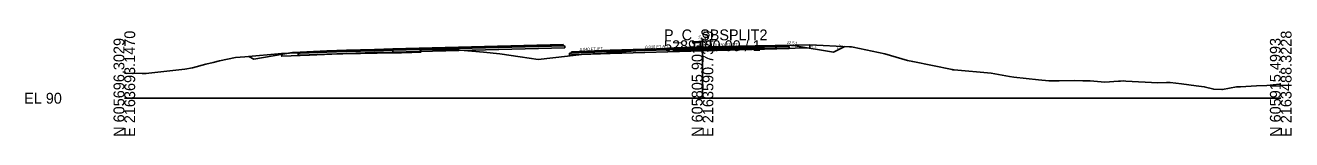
# Model space of a CAD drawing. Extents: x -26 to 1303, y -10 to 12033.
# Drawn here: x -25.7 to 302.8, y 4990.3 to 5017.8 of the extents above; entities that cross this region are included whole.
import ezdxf

# ---------------------------------------------------------------- set-up
doc = ezdxf.new("R2010")
doc.units = 0
for name, color, linetype in [('RD_GPK_XS_Cell', 7, 'Continuous'), ('RD_XS_Base', 7, 'Continuous'), ('RD_XS_ExGround', 7, 'Continuous'), ('RD_XS_ExPaveRet', 7, 'Continuous'), ('RD_XS_Greenside', 7, 'Continuous'), ('RD_XS_Pave', 7, 'Continuous'), ('RD_XS_PaveOvlay_CP', 7, 'Continuous'), ('RD_XS_TieSlope', 7, 'Continuous'), ('RD_XS_TX_Elev_EX', 7, 'Continuous'), ('RD_XS_TX_Elev_PR', 7, 'Continuous'), ('RD_XS_TX_ShdSlope', 7, 'Continuous'), ('RD_XS_TX_Slope', 7, 'Continuous')]:
    doc.layers.add(name, color=color, linetype=linetype)

msp = doc.modelspace()

# ---------------------------------------------------------------- linework, layer by layer
at = {"layer": 'RD_GPK_XS_Cell'}
for p, q in [((150, 5000), (150, 5015)), ((0, 5000), (150, 5000)), ((150, 5000), (300, 5000))]:
    msp.add_line(p, q, dxfattribs=at)
at = {"layer": 'RD_XS_Base'}
for p, q in [((69.61, 5012.43), (114.3, 5013.59)), ((113.8, 5013.58), (113.8, 5013.58)), ((114.3, 5013.59), (114.3, 5013.09)), ((114.3, 5013.56), (114.3, 5013.56)), ((172.5, 5013.41), (172.5, 5012.91)), ((45.39, 5011.63), (45.11, 5011.62)), ((45.11, 5011.62), (45.11, 5011.4)), ((45.11, 5011.4), (45.11, 5011.12)), ((45.11, 5011.12), (45.39, 5011.13)), ((45.61, 5011.64), (45.39, 5011.63)), ((45.39, 5011.13), (45.61, 5011.14)), ((52.56, 5011.92), (45.61, 5011.64)), ((45.61, 5011.14), (52.56, 5011.42)), ((57.61, 5012.12), (52.56, 5011.92)), ((52.56, 5011.42), (57.61, 5011.62)), ((64.91, 5012.31), (57.61, 5012.12)), ((57.61, 5011.62), (64.91, 5011.81)), ((69.61, 5012.43), (64.91, 5012.31)), ((64.91, 5011.81), (69.61, 5011.93)), ((114.3, 5013.09), (69.61, 5011.93)), ((69.61, 5011.93), (69.61, 5012.59)), ((69.61, 5012.59), (69.61, 5012.59)), ((69.61, 5012.59), (69.61, 5012.59)), ((69.61, 5012.59), (69.61, 5012.43)), ((69.61, 5012.43), (69.61, 5012.43)), ((69.61, 5011.93), (69.61, 5012.43)), ((69.61, 5012.43), (69.61, 5012.43)), ((69.61, 5012.43), (69.61, 5012.43)), ((69.61, 5011.93), (69.61, 5011.93)), ((93.61, 5013.06), (93.61, 5013.06)), ((93.61, 5013.06), (93.61, 5013.06)), ((93.61, 5012.56), (93.61, 5012.56)), ((93.61, 5012.56), (93.61, 5012.56)), ((116, 5011.71), (115.5, 5011.69)), ((115.5, 5011.69), (115.5, 5011.69)), ((115.5, 5011.69), (115.5, 5011.19)), ((115.5, 5011.19), (116, 5011.21)), ((126, 5012.11), (116, 5011.71)), ((116, 5011.71), (116, 5011.71)), ((116, 5011.21), (126, 5011.61)), ((116, 5011.21), (116, 5011.21)), ((150, 5012.78), (126, 5012.11)), ((126, 5011.61), (150, 5012.28)), ((126, 5012.11), (126, 5012.11)), ((126, 5011.61), (126, 5011.61)), ((150, 5012.78), (172, 5013.39)), ((150, 5012.28), (150, 5012.94)), ((150, 5012.94), (150, 5012.94)), ((150, 5012.94), (150, 5012.94)), ((150, 5012.94), (150, 5012.78)), ((172.5, 5012.91), (150, 5012.28)), ((150, 5012.78), (150, 5012.78)), ((150, 5012.28), (150, 5012.78)), ((150, 5012.78), (150, 5012.78)), ((150, 5012.78), (150, 5012.78)), ((150, 5012.28), (150, 5012.28)), ((162, 5013.11), (162, 5013.11)), ((162, 5013.11), (162, 5013.11)), ((162, 5012.61), (162, 5012.61)), ((162, 5012.61), (162, 5012.61)), ((172, 5013.39), (172, 5013.39)), ((172.5, 5013.37), (172.5, 5013.37))]:
    msp.add_line(p, q, dxfattribs=at)
at = {"layer": 'RD_XS_ExGround'}
msp.add_lwpolyline([(0, 5006.53), (4.66, 5006.44), (5.67, 5006.44), (6.31, 5006.51), (15.68, 5007.53), (17.65, 5007.89), (21.17, 5008.82), (23, 5009.26), (24.69, 5009.69), (28.82, 5010.51), (31.24, 5010.72), (40.84, 5011.6), (58.79, 5012.34), (59.16, 5012.35), (59.38, 5012.35), (60.86, 5012.36), (60.94, 5012.36), (61.19, 5012.36), (61.72, 5012.38), (62.25, 5012.38), (66.75, 5012.49), (71.93, 5012.54), (76.88, 5012.64), (83.64, 5012.53), (85.15, 5012.5), (87.13, 5012.43), (93.18, 5011.93), (97.43, 5011.5), (102.71, 5010.73), (107.34, 5010.07), (114.99, 5010.92), (118.61, 5011.3), (121.5, 5011.53), (123.5, 5011.52), (126.58, 5011.84), (133.91, 5012.36), (141.14, 5012.93), (142.63, 5013.03), (145.13, 5013.1), (151.45, 5013.27), (152.91, 5013.32), (155.38, 5013.35), (158.18, 5013.4), (159.67, 5013.48), (159.87, 5013.5), (160.14, 5013.5), (163.67, 5013.57), (174, 5013.73), (177.87, 5013.8), (188.14, 5013.29), (188.68, 5013.27), (189.08, 5013.18), (197.3, 5011.52), (197.32, 5011.51), (203.19, 5009.81), (204.53, 5009.5), (214.76, 5007.41), (214.93, 5007.37), (215.31, 5007.34), (224.86, 5006.49), (229.6, 5005.67), (230.79, 5005.49), (237.15, 5004.73), (239.8, 5004.49), (242.52, 5004.49), (246.46, 5004.62), (248.63, 5004.47), (250.55, 5004.49), (254.41, 5004.12), (257.91, 5004.42), (258.45, 5004.44), (259.22, 5004.52), (259.85, 5004.43), (268.09, 5004.02), (270.34, 5004.11), (271.31, 5004.09), (274.27, 5003.71), (278.06, 5003.17), (280.16, 5002.96), (282.61, 5002.34), (284.71, 5002.25), (284.85, 5002.25), (284.93, 5002.27), (288.56, 5002.91), (289.55, 5002.92), (293.69, 5003.23), (296.36, 5003.33), (299.66, 5003.6), (300, 5003.62)], dxfattribs=at)
at = {"layer": 'RD_XS_ExPaveRet'}
for points in [[(177.87, 5013.8), (177.87, 5013.05), (177.87, 5013.05), (177.87, 5013.05), (174, 5012.98), (174, 5012.98), (163.67, 5012.82), (163.67, 5012.82), (160.14, 5012.75), (160.14, 5012.75), (159.87, 5012.75), (159.67, 5012.73), (159.67, 5012.73), (158.18, 5012.65), (158.18, 5012.65), (158.18, 5012.65), (158.18, 5012.65), (155.38, 5012.6), (155.38, 5012.6), (152.91, 5012.57), (151.45, 5012.52), (151.45, 5012.52), (145.13, 5012.35), (145.13, 5012.35), (142.63, 5012.28), (142.63, 5013.03), (142.63, 5013.03), (145.13, 5013.1), (145.13, 5013.1), (151.45, 5013.27), (151.45, 5013.27), (152.91, 5013.32), (155.38, 5013.35), (155.38, 5013.35), (158.18, 5013.4), (158.18, 5013.4), (158.18, 5013.4), (158.18, 5013.4), (159.67, 5013.48), (159.67, 5013.48), (159.87, 5013.5), (160.14, 5013.5), (160.14, 5013.5), (163.67, 5013.57), (163.67, 5013.57), (174, 5013.73), (174, 5013.73), (177.87, 5013.8), (177.87, 5013.8)], [(177.87, 5013.8), (174, 5013.73), (163.67, 5013.57), (160.14, 5013.5), (159.87, 5013.5), (159.67, 5013.48), (158.18, 5013.4), (155.38, 5013.35), (152.91, 5013.32), (151.45, 5013.27), (145.13, 5013.1), (142.63, 5013.03), (142.63, 5012.28), (145.13, 5012.35), (151.45, 5012.52), (152.91, 5012.57), (155.38, 5012.6), (158.18, 5012.65), (159.67, 5012.73), (159.87, 5012.75), (160.14, 5012.75), (163.67, 5012.82), (174, 5012.98), (177.87, 5013.05), (177.87, 5013.05), (177.87, 5013.8), (177.87, 5013.8)], [(76.88, 5012.64), (76.88, 5012.64), (74.59, 5012.6), (71.93, 5012.54), (68.01, 5012.5), (66.75, 5012.49), (65.6, 5012.46), (64.86, 5012.46), (62.37, 5012.4), (61.63, 5012.38), (61.27, 5012.37), (60.94, 5012.36), (60.83, 5012.36), (60.1, 5012.35), (59.43, 5012.35), (59, 5012.34), (56.71, 5012.26), (55.81, 5012.21), (48.07, 5011.9), (40.84, 5011.6), (40.84, 5011.21), (40.84, 5010.85), (48.07, 5011.15), (55.81, 5011.46), (56.71, 5011.51), (59, 5011.59), (59.43, 5011.6), (60.1, 5011.6), (60.83, 5011.61), (60.94, 5011.61), (61.27, 5011.62), (61.63, 5011.63), (62.37, 5011.65), (64.86, 5011.71), (65.6, 5011.71), (66.75, 5011.74), (68.01, 5011.75), (71.93, 5011.79), (74.59, 5011.85), (76.88, 5011.89), (76.88, 5011.89), (76.88, 5011.89), (76.88, 5012.34), (76.88, 5012.64), (76.88, 5012.64)], [(76.88, 5012.64), (76.88, 5012.64), (74.59, 5012.6), (71.93, 5012.54), (68.01, 5012.5), (66.75, 5012.49), (65.6, 5012.46), (64.86, 5012.46), (62.37, 5012.4), (61.63, 5012.38), (61.27, 5012.37), (60.94, 5012.36), (60.83, 5012.36), (60.1, 5012.35), (59.43, 5012.35), (59, 5012.34), (56.71, 5012.26), (55.81, 5012.21), (48.07, 5011.9), (40.84, 5011.6), (40.84, 5011.21), (40.84, 5010.85), (48.07, 5011.15), (55.81, 5011.46), (56.71, 5011.51), (59, 5011.59), (59.43, 5011.6), (60.1, 5011.6), (60.83, 5011.61), (60.94, 5011.61), (61.27, 5011.62), (61.63, 5011.63), (62.37, 5011.65), (64.86, 5011.71), (65.6, 5011.71), (66.75, 5011.74), (68.01, 5011.75), (71.93, 5011.79), (74.59, 5011.85), (76.88, 5011.89), (76.88, 5011.89), (76.88, 5011.89), (76.88, 5012.34), (76.88, 5012.64), (76.88, 5012.64)]]:
    msp.add_lwpolyline(points, dxfattribs=at)
at = {"layer": 'RD_XS_Greenside'}
for p, q in [((174, 5013.55), (184, 5011.89)), ((33.61, 5010.13), (32.25, 5010.81)), ((43.61, 5011.8), (33.61, 5010.13)), ((184, 5011.89), (186.93, 5013.35))]:
    msp.add_line(p, q, dxfattribs=at)
at = {"layer": 'RD_XS_Pave'}
for p, q in [((113.8, 5013.9), (69.61, 5012.75)), ((113.8, 5013.74), (69.61, 5012.59)), ((69.61, 5012.59), (113.8, 5013.74)), ((69.61, 5012.43), (113.8, 5013.58)), ((113.8, 5013.74), (113.8, 5013.9)), ((113.8, 5013.9), (113.8, 5013.9)), ((113.8, 5013.58), (113.8, 5013.74)), ((113.8, 5013.74), (113.8, 5013.74)), ((172, 5013.71), (150, 5013.1)), ((172, 5013.55), (150, 5012.94)), ((150, 5012.94), (172, 5013.55)), ((150, 5012.78), (172.5, 5013.41)), ((162, 5013.43), (162, 5013.43)), ((162, 5013.43), (162, 5013.43)), ((172, 5013.55), (172, 5013.71)), ((172, 5013.71), (172, 5013.71)), ((172, 5013.39), (172, 5013.55)), ((172, 5013.55), (172, 5013.55)), ((52.56, 5012.24), (45.61, 5011.96)), ((45.61, 5011.8), (52.56, 5012.08)), ((52.56, 5012.08), (45.61, 5011.8)), ((45.61, 5011.96), (45.61, 5011.89)), ((45.61, 5011.64), (52.56, 5011.92)), ((45.61, 5011.89), (45.61, 5011.8)), ((45.61, 5011.8), (45.61, 5011.73)), ((45.61, 5011.73), (45.61, 5011.64)), ((57.61, 5012.44), (52.56, 5012.24)), ((52.56, 5012.08), (57.61, 5012.28)), ((57.61, 5012.28), (52.56, 5012.08)), ((52.56, 5011.92), (57.61, 5012.12)), ((64.91, 5012.63), (57.61, 5012.44)), ((57.61, 5012.28), (64.91, 5012.47)), ((64.91, 5012.47), (57.61, 5012.28)), ((57.61, 5012.12), (64.91, 5012.31)), ((69.61, 5012.75), (64.91, 5012.63)), ((64.91, 5012.47), (69.61, 5012.59)), ((69.61, 5012.59), (64.91, 5012.47)), ((64.91, 5012.31), (69.61, 5012.43)), ((69.61, 5012.75), (69.61, 5012.75)), ((69.61, 5012.59), (69.61, 5012.59)), ((69.61, 5012.59), (69.61, 5012.59)), ((69.61, 5012.59), (69.61, 5012.43)), ((69.61, 5012.59), (69.61, 5012.59)), ((69.61, 5012.43), (69.61, 5012.59)), ((69.61, 5012.59), (69.61, 5012.59)), ((69.61, 5012.59), (69.61, 5012.59)), ((69.61, 5012.43), (69.61, 5012.43)), ((69.61, 5012.43), (69.61, 5012.43)), ((93.61, 5013.37), (93.61, 5013.37)), ((93.61, 5013.37), (93.61, 5013.37)), ((93.61, 5013.22), (93.61, 5013.22)), ((93.61, 5013.22), (93.61, 5013.22)), ((93.61, 5013.22), (93.61, 5013.22)), ((93.61, 5013.22), (93.61, 5013.22)), ((93.61, 5013.06), (93.61, 5013.06)), ((93.61, 5013.06), (93.61, 5013.06)), ((126, 5012.42), (116, 5012.02)), ((116, 5011.87), (126, 5012.27)), ((126, 5012.27), (116, 5011.87)), ((116, 5011.71), (126, 5012.11)), ((116, 5012.02), (116, 5012.02)), ((116, 5012.02), (116, 5011.87)), ((116, 5011.87), (116, 5011.87)), ((116, 5011.87), (116, 5011.71)), ((150, 5013.1), (126, 5012.42)), ((126, 5012.27), (150, 5012.94)), ((150, 5012.94), (126, 5012.27)), ((126, 5012.11), (150, 5012.78)), ((126, 5012.42), (126, 5012.42)), ((126, 5012.27), (126, 5012.27)), ((126, 5012.27), (126, 5012.27)), ((126, 5012.11), (126, 5012.11)), ((150, 5013.1), (150, 5013.1)), ((150, 5012.94), (150, 5012.94)), ((150, 5012.94), (150, 5012.94)), ((150, 5012.94), (150, 5012.78)), ((150, 5012.94), (150, 5012.94)), ((150, 5012.78), (150, 5012.94)), ((150, 5012.94), (150, 5012.94)), ((150, 5012.94), (150, 5012.94)), ((150, 5012.78), (150, 5012.78)), ((150, 5012.78), (150, 5012.78)), ((162, 5013.27), (162, 5013.27)), ((162, 5013.27), (162, 5013.27)), ((162, 5013.27), (162, 5013.27)), ((162, 5013.27), (162, 5013.27)), ((162, 5013.11), (162, 5013.11)), ((162, 5013.11), (162, 5013.11))]:
    msp.add_line(p, q, dxfattribs=at)
at = {"layer": 'RD_XS_PaveOvlay_CP'}
for p, q in [((113.8, 5013.9), (69.61, 5012.75)), ((172, 5013.71), (150, 5013.1)), ((162, 5013.43), (162, 5013.43)), ((162, 5013.43), (162, 5013.43)), ((52.56, 5012.24), (45.61, 5011.96)), ((57.61, 5012.44), (52.56, 5012.24)), ((64.91, 5012.63), (57.61, 5012.44)), ((69.61, 5012.75), (64.91, 5012.63)), ((69.61, 5012.75), (69.61, 5012.75)), ((93.61, 5013.37), (93.61, 5013.37)), ((93.61, 5013.37), (93.61, 5013.37)), ((126, 5012.42), (116, 5012.02)), ((150, 5013.1), (126, 5012.42)), ((126, 5012.42), (126, 5012.42)), ((150, 5013.1), (150, 5013.1))]:
    msp.add_line(p, q, dxfattribs=at)
at = {"layer": 'RD_XS_TieSlope'}
for p, q in [((172, 5013.71), (174, 5013.55)), ((45.61, 5011.96), (43.61, 5011.8))]:
    msp.add_line(p, q, dxfattribs=at)

# ---------------------------------------------------------------- texts
at = {"layer": 'RD_GPK_XS_Cell'}
for s, p in [('E 2163693.1470', (2.8, 4990)), ('E 2163590.7349', (152.8, 4990)), ('E 2163488.3228', (302.8, 4990)), ('N 605696.3029', (0, 4990)), ('N 605805.9011', (150, 4990)), ('N 605915.4993', (300, 4990))]:
    msp.add_text(s, height=2.8, rotation=90, dxfattribs=at).set_placement(p)
for s, p in [('P_C_SBSPLIT2', (140, 5015)), ('5289+00.00 / 1', (140, 5012.2)), ('EL 90', (-26, 4998.6))]:
    msp.add_text(s, height=2.8, dxfattribs=at).set_placement(p)
at = {"layer": 'RD_XS_TX_Elev_EX'}
msp.add_text('103.23', height=0.6, rotation=90, dxfattribs=at).set_placement((149.63, 5013.7))
at = {"layer": 'RD_XS_TX_Elev_PR'}
msp.add_text('103.10', height=1, rotation=90, dxfattribs=at).set_placement((151.33, 5013.47))
at = {"layer": 'RD_XS_TX_ShdSlope'}
msp.add_text('12.5:1', height=0.75, rotation=355.4261, dxfattribs=at).set_placement((171.84, 5014.07))
at = {"layer": 'RD_XS_TX_Slope'}
for s, rotation, p in [('0.030 FT./FT.', 1.7184, (135.16, 5012.84)), ('0.030 FT./FT.', 1.7184, (153.16, 5013.38)), ('6:1', 350.5358, (178.13, 5013.26)), ('2:1', 26.5651, (184.86, 5012.74)), ('0.040 FT./FT.', 2.2906, (118.15, 5012.25))]:
    msp.add_text(s, height=0.75, rotation=rotation, dxfattribs=at).set_placement(p)

doc.saveas('drawing.dxf')
